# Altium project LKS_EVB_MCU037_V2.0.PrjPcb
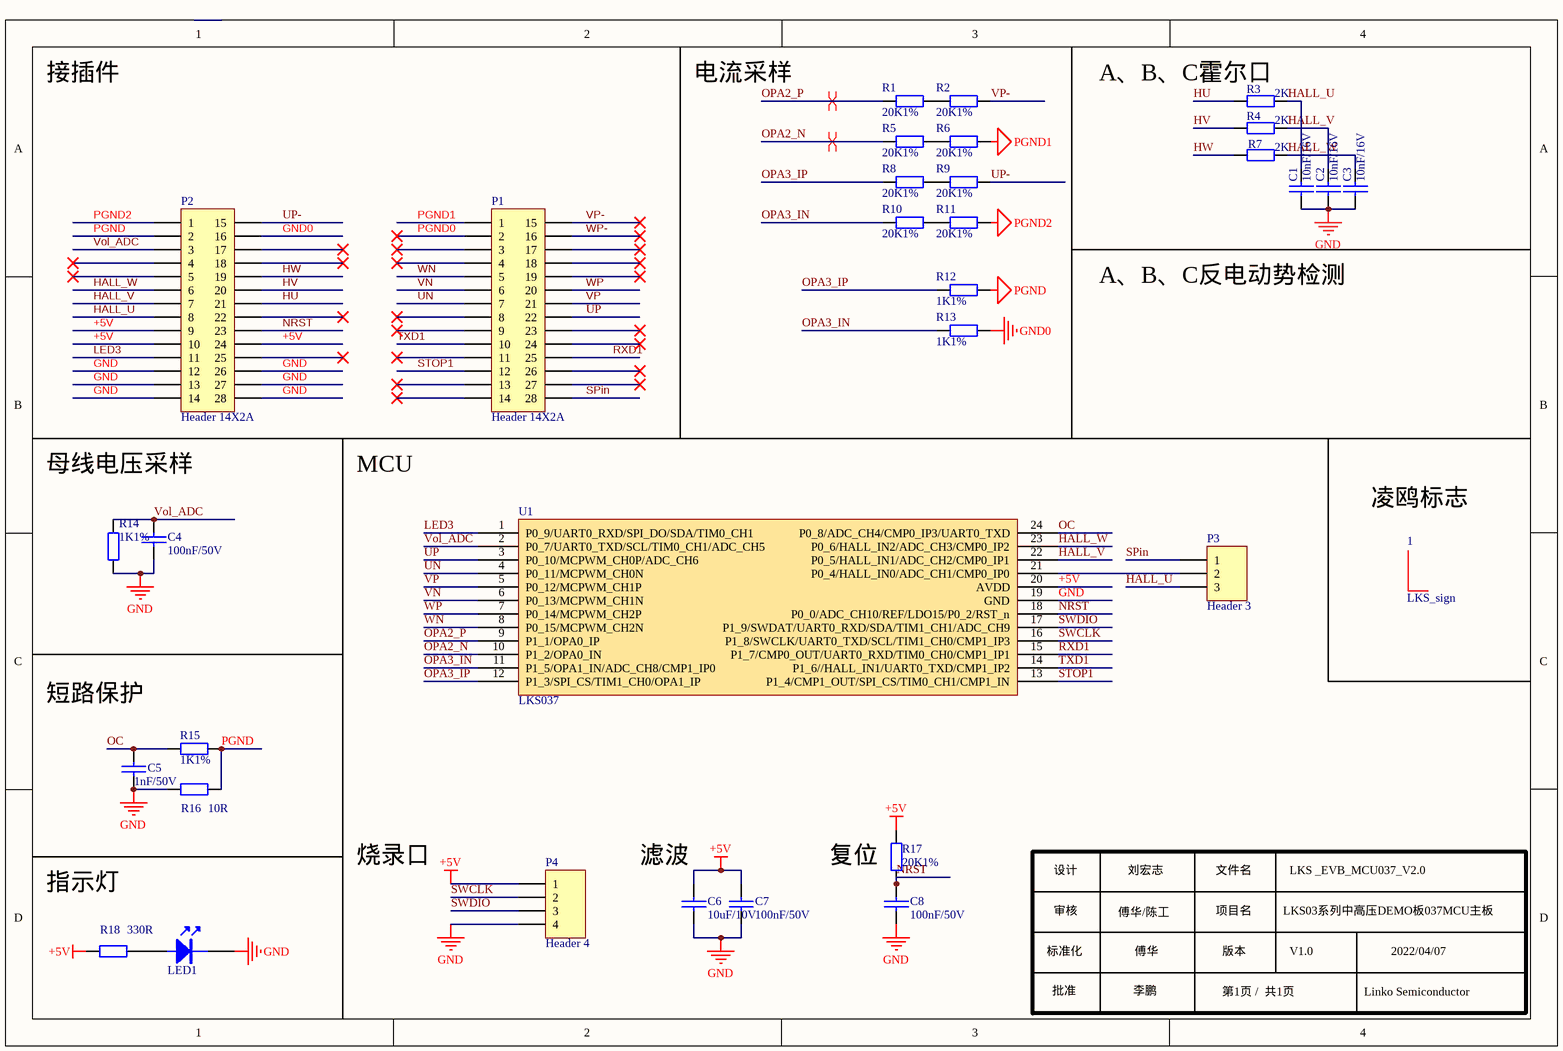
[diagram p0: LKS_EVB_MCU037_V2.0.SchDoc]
1 sheet, 33 parts. Net scope: global (net labels, ports and power ports of the same name join across sheets).
Board file: LKS_EVB_MCU037_V2.0.PcbDoc

## Sheet LKS_EVB_MCU037_V2.0.SchDoc
size A4; SheetNumber: 1; SheetTotal: 1

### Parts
1  LKS_sign  [LKS_LOGO2]
C1  10nF/16V  [0603C]
C2  10nF/16V  [0603C]
C3  10nF/16V  [0603C]
C4  100nF/50V  [0603C]
C5  1nF/50V  [0603C]
C6  10uF/10V  [0603C]
C7  100nF/50V  [0603C]
C8  100nF/50V  [0603C]
LED1  LED  [0603D]  (value not drawn)
P1  Header 14X2A  [HDR2X14_CEN]
P2  Header 14X2A  [HDR2X14_CEN]
P3  Header 3  [HDR1X3]
P4  Header 4  [HDR1X4]
R1  20K1%  [0603R]
R2  20K1%  [0603R]
R3  2K  [0603R]
R4  2K  [0603R]
R5  20K1%  [0603R]
R6  20K1%  [0603R]
R7  2K  [0603R]
R8  20K1%  [0603R]
R9  20K1%  [0603R]
R10  20K1%  [0603R]
R11  20K1%  [0603R]
R12  1K1%  [0603R]
R13  1K1%  [0603R]
R14  1K1%  [0603R]
R15  1K1%  [0603R]
R16  10R  [0603R]
R17  20K1%  [0603R]
R18  330R  [0603R]
U1  LKS037  [SSOP24]

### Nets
+5V: C6.2 C7.2 P2.9 P2.10 P2.24 P4.1 R17.2 R18.1 U1.20(AVDD)
GND: C1.2 C2.2 C3.2 C4.1 C5.1 C6.1 C7.1 C8.2 LED1.2(K) P2.12 P2.13 P2.14 P2.26 P2.27 P2.28 P4.4 R14.1 R16.2 U1.19(GND)
GND0: P2.16 R13.1
PGND: P2.2 R12.1 R15.2 R16.1
PGND1: P1.1 R6.1
PGND2: P2.1 R11.1
HALL_U: C1.1 P2.8 P3.3 R3.2
HALL_V: C2.1 P2.7 R4.2 U1.22(P0_5/HALL_IN1/ADC_CH2/CMP0_IP1)
HALL_W: C3.1 P2.6 R7.2 U1.23(P0_6/HALL_IN2/ADC_CH3/CMP0_IP2)
HU: P2.21 R3.1
HV: P2.20 R4.1
HW: P2.19 R7.1
LED3: P2.11 U1.1(P0_9/UART0_RXD/SPI_DO/SDA/TIM0_CH1)
NRST: C8.1 P2.23 R17.1 U1.18(P0_0/ADC_CH10/REF/LDO15/P0_2/RST_n)
OC: C5.2 R15.1 U1.24(P0_8/ADC_CH4/CMP0_IP3/UART0_TXD)
OPA2_N: R5.2 U1.10(P1_2/OPA0_IN)
OPA2_P: R1.2 U1.9(P1_1/OPA0_IP)
OPA3_IN: R10.2 R13.2 U1.11(P1_5/OPA1_IN/ADC_CH8/CMP1_IP0)
OPA3_IP: R8.2 R12.2 U1.12(P1_3/SPI_CS/TIM1_CH0/OPA1_IP)
PGND0: P1.2
RXD1: P1.25 U1.15(P1_7/CMP0_OUT/UART0_RXD/TIM0_CH0/CMP1_IP1)
SPin: P1.28 P3.1
STOP1: P1.12 U1.13(P1_4/CMP1_OUT/SPI_CS/TIM0_CH1/CMP1_IN)
SWCLK: P4.2 U1.16(P1_8/SWCLK/UART0_TXD/SCL/TIM1_CH0/CMP1_IP3)
SWDIO: P4.3 U1.17(P1_9/SWDAT/UART0_RXD/SDA/TIM1_CH1/ADC_CH9)
TXD1: P1.10 U1.14(P1_6//HALL_IN1/UART0_TXD/CMP1_IP2)
UN: P1.7 U1.4(P0_11/MCPWM_CH0N)
UP: P1.22 U1.3(P0_10/MCPWM_CH0P/ADC_CH6)
UP-: P2.15 R9.1
VN: P1.6 U1.6(P0_13/MCPWM_CH1N)
Vol_ADC: C4.2 P2.3 R14.2 U1.2(P0_7/UART0_TXD/SCL/TIM0_CH1/ADC_CH5)
VP: P1.21 U1.5(P0_12/MCPWM_CH1P)
VP-: P1.15 R2.1
WN: P1.5 U1.8(P0_15/MCPWM_CH2N)
WP: P1.20 U1.7(P0_14/MCPWM_CH2P)
WP-: P1.16
NetLED1_1: LED1.1(A) R18.2
NetP3_2: P3.2 U1.21(P0_4/HALL_IN0/ADC_CH1/CMP0_IP0)
NetR1_1: R1.1 R2.2
NetR5_1: R5.1 R6.2
NetR8_1: R8.1 R9.2
NetR10_1: R10.1 R11.2

Not connected (* = marked no-connect by the designer): P1 3* 4* 8* 9* 11* 13* 14* 17* 18* 19* 23* 24* 26* 27*; P2 4* 5* 17* 18* 22* 25*

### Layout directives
differential pair: OPA2_N, OPA2_P

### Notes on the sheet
- 接插件
- 电流采样
- A、B、C霍尔口
- A、B、C反电动势检测
- 母线电压采样
- MCU
- (near 1) 凌鸥标志
- 短路保护
- 烧录口
- (near C6) 滤波
- 复位
- 指示灯
- 设计
- 审核
- 傅华/陈工
- 刘宏志
- 文件名
- 项目名
- LKS03系列中高压DEMO板037MCU主板
- LKS _EVB_MCU037_V2.0
- 标准化
- 批准
- 李鹏
- 傅华
- 版本
- 第1页 /  共1页
- V1.0
- Linko Semiconductor
- 2022/04/07

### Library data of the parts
C1-C3 = CAP: Capacitor
C4-C8 = C: Capacitor
LED1 = LED: LED_Light
P1 P2 = Header 14X2A: Header, 14-Pin, Dual row
P3 = Header 3: Header, 3-Pin
P4 = Header 4: Header, 4-Pin
R1-R17 = Res: Resistor; Value: K
R18 = Res: Resistor; Value: 330
U1 = LKS32MC037M6S8: Chip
